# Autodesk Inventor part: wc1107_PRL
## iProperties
Shininess: 64.0
Length Units: 11272
Angle Units: 11279
Time Units: 11290
Mass Units: 11286
Length Display Precision: 3
Angle Display Precision: 2
Compacted: True
Part Number: wc1107_PRL
Document SubType Name: Modeling
Created: 2004-08
Designer: John Blackburn
Manufacturer: Standard
Standards Organization: Custom
Material: Phenolic
Density: 0.0
Volumn: 0.0
Area: 0.0
PropertySet Name: Model Information
Control State: 0
Master: False
Checked Out: False
Author: John Blackburn
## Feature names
1. Revolution1
